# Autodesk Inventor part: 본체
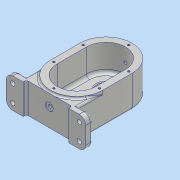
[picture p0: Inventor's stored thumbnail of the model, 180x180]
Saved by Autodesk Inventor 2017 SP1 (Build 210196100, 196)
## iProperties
Part Number: 본체
Material: 알루미늄 6061
Document SubType Name: Modeling
Designer: MRC
Density: 2.7 g/cm^3
Appearance: 알루미늄 - 평지
Mass: 756.742 g
Surface Area: 581.677 cm^2
Volume: 280.275 cm^3
Author: MRC
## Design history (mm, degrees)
sketch "스케치1"
  geometry: L1 (0, 0)-(0, -45); L2 (-40, 0)-(-40, -45); L3 (40, -45)-(40, 0); A1 r 40 centre (0, 0) between (40, 0) and (-40, 0); A2 r 40 centre (0, -45) between (-40, -45) and (40, -45); 1 further point
  constraints: 8 end point, 4 point on circle, 4 tangent, 2 centre point, 1 midpoint, 1 parallel, 1 vertical
  dimensions: "d0" = 45 distance of L1.start L1.end; "d1" = 80 diameter of A2
extrude "돌출1" new body sketch "스케치1" distance "d2" = 21; taper "d4" = 0 deg; dims "d3" = 28, "d5" = 0
sketch "스케치2"
  geometry: L1 (-40, 0)-(-40, -45) reference; L2 (40, -45)-(40, 0) reference; L3 (-30, 0)-(-30, -45); L4 (30, -45)-(30, 0); A1 r 40 centre (0, -45) between (-40, -45) and (40, -45) reference; A2 r 40 centre (0, 0) between (40, 0) and (-40, 0) reference; A3 r 30 centre (0, -45) between (-30, -45) and (30, -45); A4 r 30 centre (0, 0) between (30, 0) and (-30, 0)
  constraints: 4 end point, 4 point on circle, 2 centre point, 3 other
  dimensions: "d6" = 10 radial gap between concentric circles of A2 A4
extrude "돌출2" cut sketch "스케치2" distance "d7" = 41; taper "d8" = 0 deg
sketch "스케치3"
  geometry: L1 (0, 0)-(0, -45); L2 (-26, 0)-(-26, -45); L3 (26, -45)-(26, 0); A1 r 40 centre (0, 0) between (40, 0) and (-40, 0) reference; A2 r 40 centre (0, -45) between (-40, -45) and (40, -45) reference; A3 r 26 centre (0, 0) between (26, 0) and (-26, 0); A4 r 26 centre (0, -45) between (-26, -45) and (26, -45); 1 further point
  constraints: 8 end point, 4 point on circle, 4 tangent, 2 centre point, 1 midpoint, 1 parallel, 1 vertical
  dimensions: "d9" = 52 diameter of A4
extrude "돌출3" join sketch "스케치3" distance "d10" = 11; taper "d11" = 0 deg
sketch "스케치4"
  geometry: L1 (-26, 0)-(-26, -45) reference; L2 (26, -45)-(26, 0) reference; L3 (-26, -30)-(26, -30); A1 r 26 centre (0, 0) between (26, 0) and (-26, 0) reference
  constraints: 2 end point, 2 point on line, 1 perpendicular
  dimensions: "d12" = 30 distance from line of A1.centre L3
extrude "돌출4" cut sketch "스케치4" distance "d13" = 3; taper "d14" = 0 deg
sketch "스케치5"
  geometry: A1 r 30 centre (0, 0) between (30, 0) and (-30, 0) reference
hole "구멍1" sketch "스케치5" at (0, 0) diameter "d15" = 22; stored, may be unused: countersink angle "d19" = 90 deg, drill point angle "d21" = 118 deg; dims "d16" = 6, "d17" = 28, "d18" = 8, "d20" = 8
sketch "스케치6"
  geometry: A1 r 30 centre (0, -45) between (-30, -45) and (30, -45) reference
hole "구멍2" sketch "스케치6" at (0, -45) diameter "d22" = 20; stored, may be unused: countersink angle "d26" = 90 deg, drill point angle "d28" = 0 deg; dims "d23" = 6, "d24" = 28, "d25" = 8, "d27" = 12
sketch "스케치7"
  geometry: C1 r 11 at (0, 0) reference
hole "구멍3" sketch "스케치7" at (0, 0) diameter "d29" = 28; stored, may be unused: countersink angle "d33" = 90 deg, drill point angle "d35" = 0 deg; dims "d30" = 6, "d31" = 28, "d32" = 8, "d34" = 4
sketch "스케치8"
  geometry: A1 r 30 centre (0, -45) between (-30, -45) and (30, -45) reference; 1 further point
  constraints: 1 horizontal alignment
  dimensions: "d36" = 35 distance of point (-35, -45) A1.centre
hole "구멍4" sketch "스케치8" at (-35, -45) diameter "d37" = 3.242; stored, may be unused: countersink angle "d41" = 90 deg, drill point angle "d43" = 118 deg; dims "d38" = 8, "d39" = 28, "d40" = 8, "d42" = 10
sketch "스케치9"
  geometry: A1 r 30 centre (0, 0) between (30, 0) and (-30, 0) reference; 1 further point
  constraints: 1 horizontal alignment
  dimensions: "d47" = 35 distance of point (-35, 0) A1.centre
hole "구멍5" sketch "스케치9" at (-35, 0) diameter "d48" = 3.242; stored, may be unused: countersink angle "d52" = 90 deg, drill point angle "d54" = 118 deg; dims "d49" = 8, "d50" = 28, "d51" = 8, "d53" = 10
node "작업 평면1"
sketch "스케치10"
  geometry: L1 (61, -28)-(-61, -28); L2 (-61, -28)-(-61, 18); L3 (-61, 18)-(61, 18); L4 (61, 18)-(61, -28); L5 (61, -28)-(-61, 18); L6 (-61, -28)-(61, 18); L7 (-26, -39)-(26, -39) reference; 3 further points
  constraints: 12 end point, 3 midpoint, 2 parallel, 1 horizontal, 1 perpendicular, 1 vertical alignment
  dimensions: "d59" = 122 distance of L2.end L3.end; "d60" = 46 distance of L1.end L2.end; "d61" = 11 distance between parallel lines of L7 L1
extrude "돌출5" join sketch "스케치10" distance "d62" = 10; taper "d63" = 0 deg
sketch "스케치11"
  geometry: L1 (21, 28.89)-(21, 13.881); L2 (21, 92)-(21, 47) reference; 1 further point
  constraints: 2 end point, 1 collinear, 1 vertical
feature "리브1" sketch "스케치11" dims "d64" = 1, "d65" = 46, "d66" = 0, "d67" = 0, "d68" = 1, "d69" = 1
node "작업 평면2"
sketch "스케치12"
  geometry: C1 r 6 at (0, 0); 1 further point
  constraints: 1 centre point, 1 coincident
  dimensions: "d71" = 12 diameter of C1
extrude "돌출6" join sketch "스케치12" stored distance "d72" = 10; taper "d73" = 0 deg
sketch "스케치13"
  geometry: C1 r 6 at (0, 0) reference
hole "구멍6" sketch "스케치13" at (0, 0) diameter "d74" = 4.917; stored, may be unused: countersink angle "d78" = 90 deg, drill point angle "d80" = 118 deg; dims "d75" = 12, "d76" = 28, "d77" = 8, "d79" = 17.1
sketch "스케치14"
  geometry: L1 (61, 18)-(-61, 18) reference; L2 (-61, -28)-(61, -28) reference; L3 (35, 18)-(-35, 18); L4 (-35, 18)-(-35, -28); L5 (-35, -28)-(35, -28); L6 (35, -28)-(35, 18); 1 further point
  constraints: 8 end point, 2 collinear, 2 parallel, 1 horizontal, 1 perpendicular
  dimensions: "d81" = 70 distance between parallel lines of L4 L6; "d82" = 35 distance from line of L4 point (0, 0) (= 0.5 x d81)
extrude "돌출7" cut sketch "스케치14" distance "d83" = 5; taper "d84" = 0 deg
sketch "스케치15"
  geometry: 1 further point
hole "구멍7" sketch "스케치15" at (0, 0) diameter "d85" = 4.917; stored, may be unused: countersink angle "d89" = 90 deg, drill point angle "d91" = 118 deg; dims "d86" = 12, "d87" = 12, "d88" = 1, "d90" = 17.1
fillet "모깎기1" dims "d92" = 10
sketch "스케치16"
  geometry: L1 (-61, 18)-(-61, -8) reference; L2 (-51, -18)-(-40, -18) reference; L3 (-40, -18)-(-40, 28) reference; L4 (-40, 28)-(-51, 28) reference; A1 r 10 centre (51, 18) between (61, 18) and (51, 28) reference; A2 r 10 centre (51, -8) between (51, -18) and (61, -8) reference; A3 r 10 centre (-51, 18) between (-51, 28) and (-61, 18) reference; A4 r 10 centre (-51, -8) between (-61, -8) and (-51, -18) reference; 1 further point
hole "구멍8" sketch "스케치16" at (-51, 18), (-51, -8), (51, 18), (51, -8) diameter "d93" = 6.6; stored, may be unused: countersink angle "d97" = 90 deg, drill point angle "d99" = 118 deg; dims "d94" = 12, "d95" = 11, "d96" = 2, "d98" = 17.1
fillet "모깎기2" dims "d100" = 3
chamfer "모따기1" distance "d101" = 1; stored, may be unused: second distance "d102" = 2, angle "d103" = 45 deg
fillet "모깎기3" dims "d104" = 3, "d105" = 0.3
fillet "모깎기4" dims "d106" = 3
sketch "스케치17"
  geometry: A1 r 26 centre (0, 0) between (26, 0) and (-26, 0) reference; 1 further point
  constraints: 1 vertical alignment
  dimensions: "d107" = 20 distance of A1.centre point (0, 20)
hole "구멍9" sketch "스케치17" at (0, 20) diameter "d108" = 3.242; stored, may be unused: countersink angle "d112" = 90 deg, drill point angle "d114" = 118 deg; dims "d109" = 8, "d110" = 11, "d111" = 2, "d113" = 10
sketch "스케치18"
  geometry: L1 (-35, -92)-(-51, -92) reference; A1 r 29 centre (0, 0) between (29, 0) and (-29, 0) reference; 1 further point
  constraints: 1 vertical alignment, 1 other
  dimensions: "d118" = 12 distance from line of L1 point (0, -80)
feature "엠보싱1" sketch "스케치18" dims "d0" = 45, "d1" = 80, "d119" = 0.5, "d120" = 0
fillet "모깎기5" dims "d121" = 5
node "솔리드1"
pattern_circular "원형 패턴1" dims angle "d45" = 180 deg
pattern_circular "원형 패턴2" dims angle "d56" = 180 deg
mirror "미러1"
pattern_circular "원형 패턴3" dims angle "d116" = 360 deg
node "투영된 루프1"
other parameters: "d58" = -92, "d70" = 43
